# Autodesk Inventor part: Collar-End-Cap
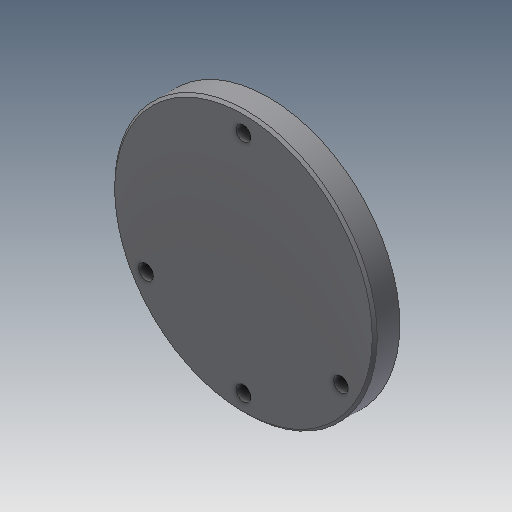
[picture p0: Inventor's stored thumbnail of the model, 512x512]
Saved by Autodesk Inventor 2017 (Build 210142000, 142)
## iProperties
Shininess: 64.0
Length Units: 11269
Angle Units: 11279
Time Units: 11290
Mass Units: 11283
Length Display Precision: 3
Angle Display Precision: 2
Compacted: True
Part Number: Collar-End-Cap
Document SubType Name: Modeling
Created: 2004-01
Designer: Administrator
Manufacturer: Standard
Standards Organization: Custom
Density: 1 g/cm^3
Material: Generic
Appearance: Default
Density: 0.0
Volumn: 0.0
Area: 0.0
PropertySet Name: Model Information
Control State: 0
Master: False
Checked Out: False
Author: Administrator
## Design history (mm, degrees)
sketch "Sketch1"
  geometry: C1 r 26.25 at (0, 0)
  constraints: 1 centre point
  dimensions: "d14" = 52.5 diameter of C1
extrude "Extrusion1" new body sketch "Sketch1" distance "d0" = 5; taper "d1" = 0 deg
sketch "Sketch2"
  geometry: C1 r 1.23 at (0, 22.5) reference; C2 r 1.23 at (-19.486, -11.25) reference; C3 r 1.23 at (0, -22.5) reference; C4 r 1.23 at (19.486, -11.25) reference
hole "Hole1" sketch "Sketch2" at (0, 22.5), (19.486, -11.25), (0, -22.5), (-19.486, -11.25) diameter "d2" = 3; stored, may be unused: countersink angle "d6" = 82 deg, drill point angle "d8" = 118 deg; dims "d3" = 6, "d4" = 4, "d5" = 2, "d7" = 8
sketch "Sketch3"
  geometry: C1 r 20 at (0, 0); C2 r 18 at (0, 0); C3 r 26.25 at (0, 0) reference
  constraints: 2 centre point, 2 concentric
  dimensions: "d15" = 36 diameter of C2; "d16" = 2 radial gap between concentric circles of C2 C1
extrude "Extrusion2" cut sketch "Sketch3" distance "d9" = 0.5; taper "d10" = 0 deg
chamfer "Chamfer1" distance "d11" = 0.5; stored, may be unused: second distance "d12" = 2, angle "d13" = 45 deg
body "Solid1"
